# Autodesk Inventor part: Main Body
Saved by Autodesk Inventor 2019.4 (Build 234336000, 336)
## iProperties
Created: 2021-01
Part Number: Main Body
Material: Generic
Document SubType Name: Modeling
Designer: Administrator
Density: 1 g/cm^3
Appearance: Default
Title: Main Body v72
Author: Administrator
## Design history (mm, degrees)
feature "Body1"
body "Solid1"
